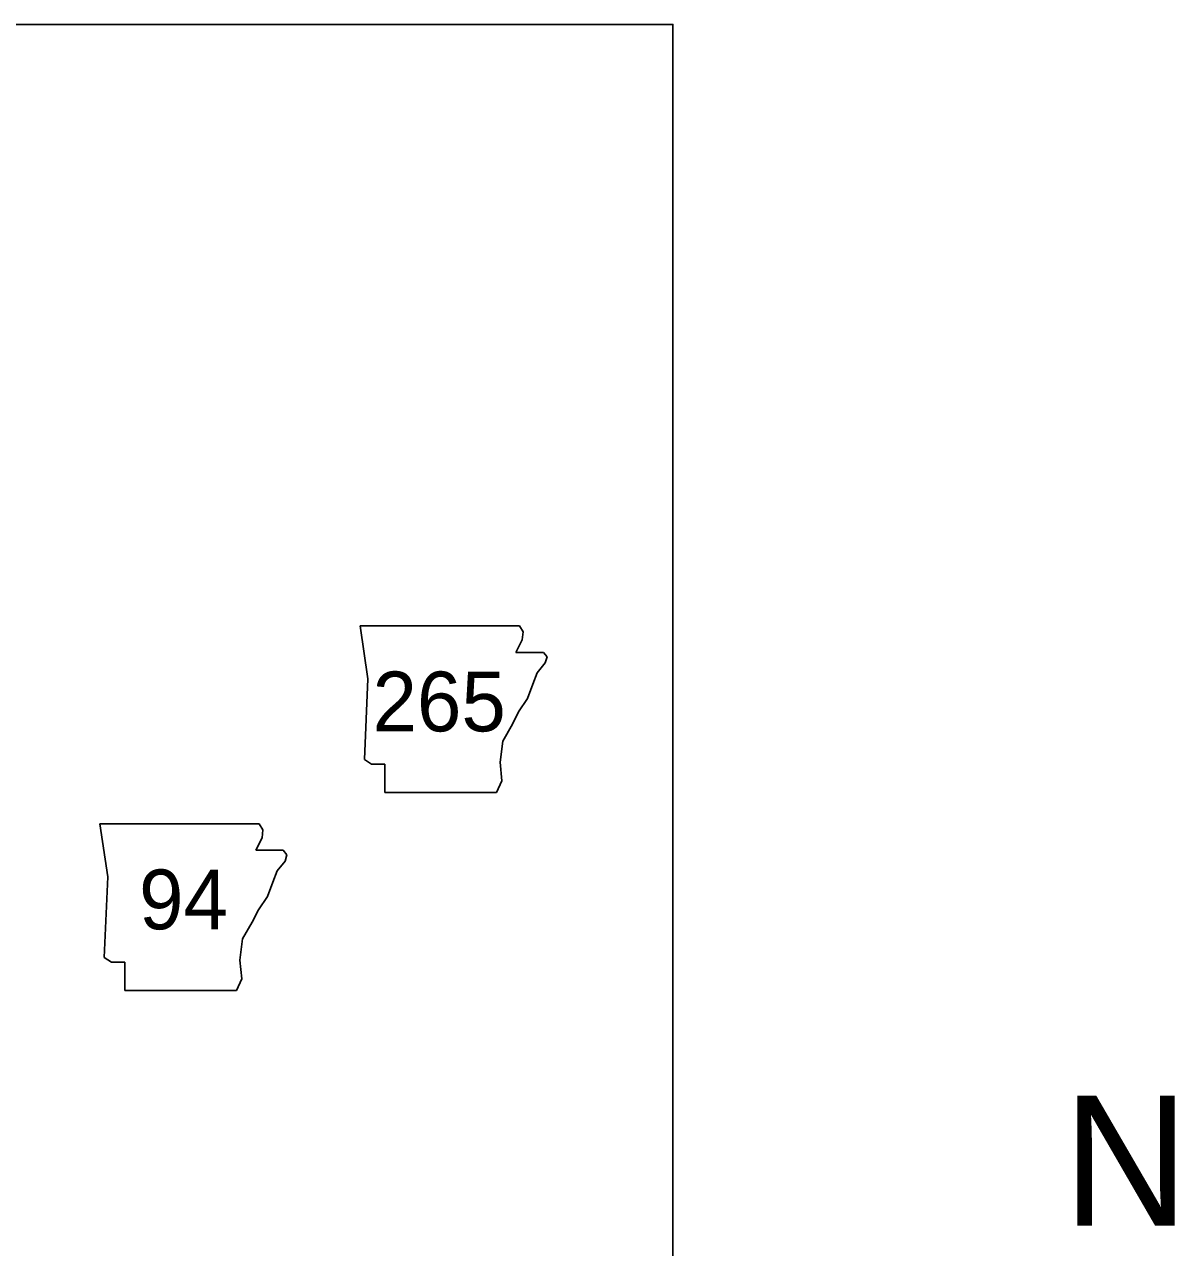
# Model space of a CAD drawing. Extents: x 6028647 to 6035072, y 5366486 to 5368495.
# Drawn here: x 6029195 to 6029359.7, y 5368270.4 to 5368445.5 of the extents above; entities that cross this region are included whole.
import ezdxf

# ---------------------------------------------------------------- set-up
doc = ezdxf.new("R2010")
doc.units = 0
for name, color, linetype in [('21', 7, 'Continuous'), ('R_Draft', 7, 'Continuous'), ('R_NoPlot', 7, 'Continuous')]:
    doc.layers.add(name, color=color, linetype=linetype)

msp = doc.modelspace()

# ---------------------------------------------------------------- linework, layer by layer
at = {"layer": '21'}
for p, q in [((6029243.08, 5368359.4), (6029244.22, 5368351.78)), ((6029266.42, 5368358.51), (6029265.9, 5368359.38)), ((6029265.41, 5368355.59), (6029266.3, 5368357.37)), ((6029266.3, 5368357.37), (6029266.42, 5368358.51)), ((6029269.34, 5368355.59), (6029265.41, 5368355.59)), ((6029269.85, 5368354.96), (6029269.34, 5368355.59)), ((6029268.45, 5368352.67), (6029269.6, 5368354.07)), ((6029269.6, 5368354.07), (6029269.85, 5368354.96)), ((6029267.82, 5368351.02), (6029268.45, 5368352.67)), ((6029244.22, 5368351.78), (6029243.71, 5368340.24)), ((6029267.06, 5368348.99), (6029267.82, 5368351.02)), ((6029265.79, 5368347.09), (6029267.06, 5368348.99)), ((6029264.9, 5368345.31), (6029265.79, 5368347.09)), ((6029263.51, 5368342.9), (6029264.9, 5368345.31)), ((6029263.13, 5368339.86), (6029263.51, 5368342.9)), ((6029243.71, 5368340.24), (6029244.73, 5368339.6)), ((6029263.38, 5368337.19), (6029263.13, 5368339.86)), ((6029244.73, 5368339.6), (6029246.63, 5368339.6)), ((6029246.63, 5368339.6), (6029246.63, 5368335.54)), ((6029262.62, 5368335.54), (6029263.38, 5368337.19)), ((6029246.63, 5368335.54), (6029262.62, 5368335.54)), ((6029205.84, 5368331.05), (6029206.98, 5368323.44)), ((6029229.19, 5368330.16), (6029228.66, 5368331.04)), ((6029229.06, 5368329.02), (6029229.19, 5368330.16)), ((6029228.17, 5368327.25), (6029229.06, 5368329.02)), ((6029232.1, 5368327.25), (6029228.17, 5368327.25)), ((6029232.61, 5368326.61), (6029232.1, 5368327.25)), ((6029232.36, 5368325.72), (6029232.61, 5368326.61)), ((6029230.58, 5368322.68), (6029231.22, 5368324.33)), ((6029231.22, 5368324.33), (6029232.36, 5368325.72)), ((6029206.98, 5368323.44), (6029206.47, 5368311.89)), ((6029229.82, 5368320.65), (6029230.58, 5368322.68)), ((6029228.55, 5368318.74), (6029229.82, 5368320.65)), ((6029227.66, 5368316.97), (6029228.55, 5368318.74)), ((6029226.27, 5368314.56), (6029227.66, 5368316.97)), ((6029225.89, 5368311.51), (6029226.27, 5368314.56)), ((6029206.47, 5368311.89), (6029207.49, 5368311.26)), ((6029207.49, 5368311.26), (6029209.39, 5368311.26)), ((6029209.39, 5368311.26), (6029209.39, 5368307.2)), ((6029226.14, 5368308.85), (6029225.89, 5368311.51)), ((6029225.38, 5368307.2), (6029226.14, 5368308.85)), ((6029209.39, 5368307.2), (6029225.38, 5368307.2))]:
    msp.add_line(p, q, dxfattribs=at)
for points in [[(6029243.08, 5368359.4), (6029265.9, 5368359.38)], [(6029205.84, 5368331.05), (6029228.66, 5368331.04)]]:
    msp.add_lwpolyline(points, dxfattribs=at)
at = {"layer": 'R_NoPlot'}
msp.add_lwpolyline([(6028702.18, 5368445.48), (6029287.88, 5368445.48), (6029287.88, 5367916.32), (6028702.18, 5367916.32)], close=True, dxfattribs=at)

# ---------------------------------------------------------------- texts
at = {"layer": '21'}
for s, p in [('265', (6029244.87, 5368344.28)), ('94', (6029211.45, 5368315.94))]:
    msp.add_text(s, height=8.554, dxfattribs=at).set_placement(p)
at = {"layer": 'R_Draft'}
msp.add_text('N', height=18.6, dxfattribs=at).set_placement((6029343.75, 5368273.53))

doc.saveas('drawing.dxf')
